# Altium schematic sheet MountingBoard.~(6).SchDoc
size Legal; Organization: Altium Limited; Address1: 3 Minna Close; Address2: Belrose; Address3: NSW 2085; Address4: Australia
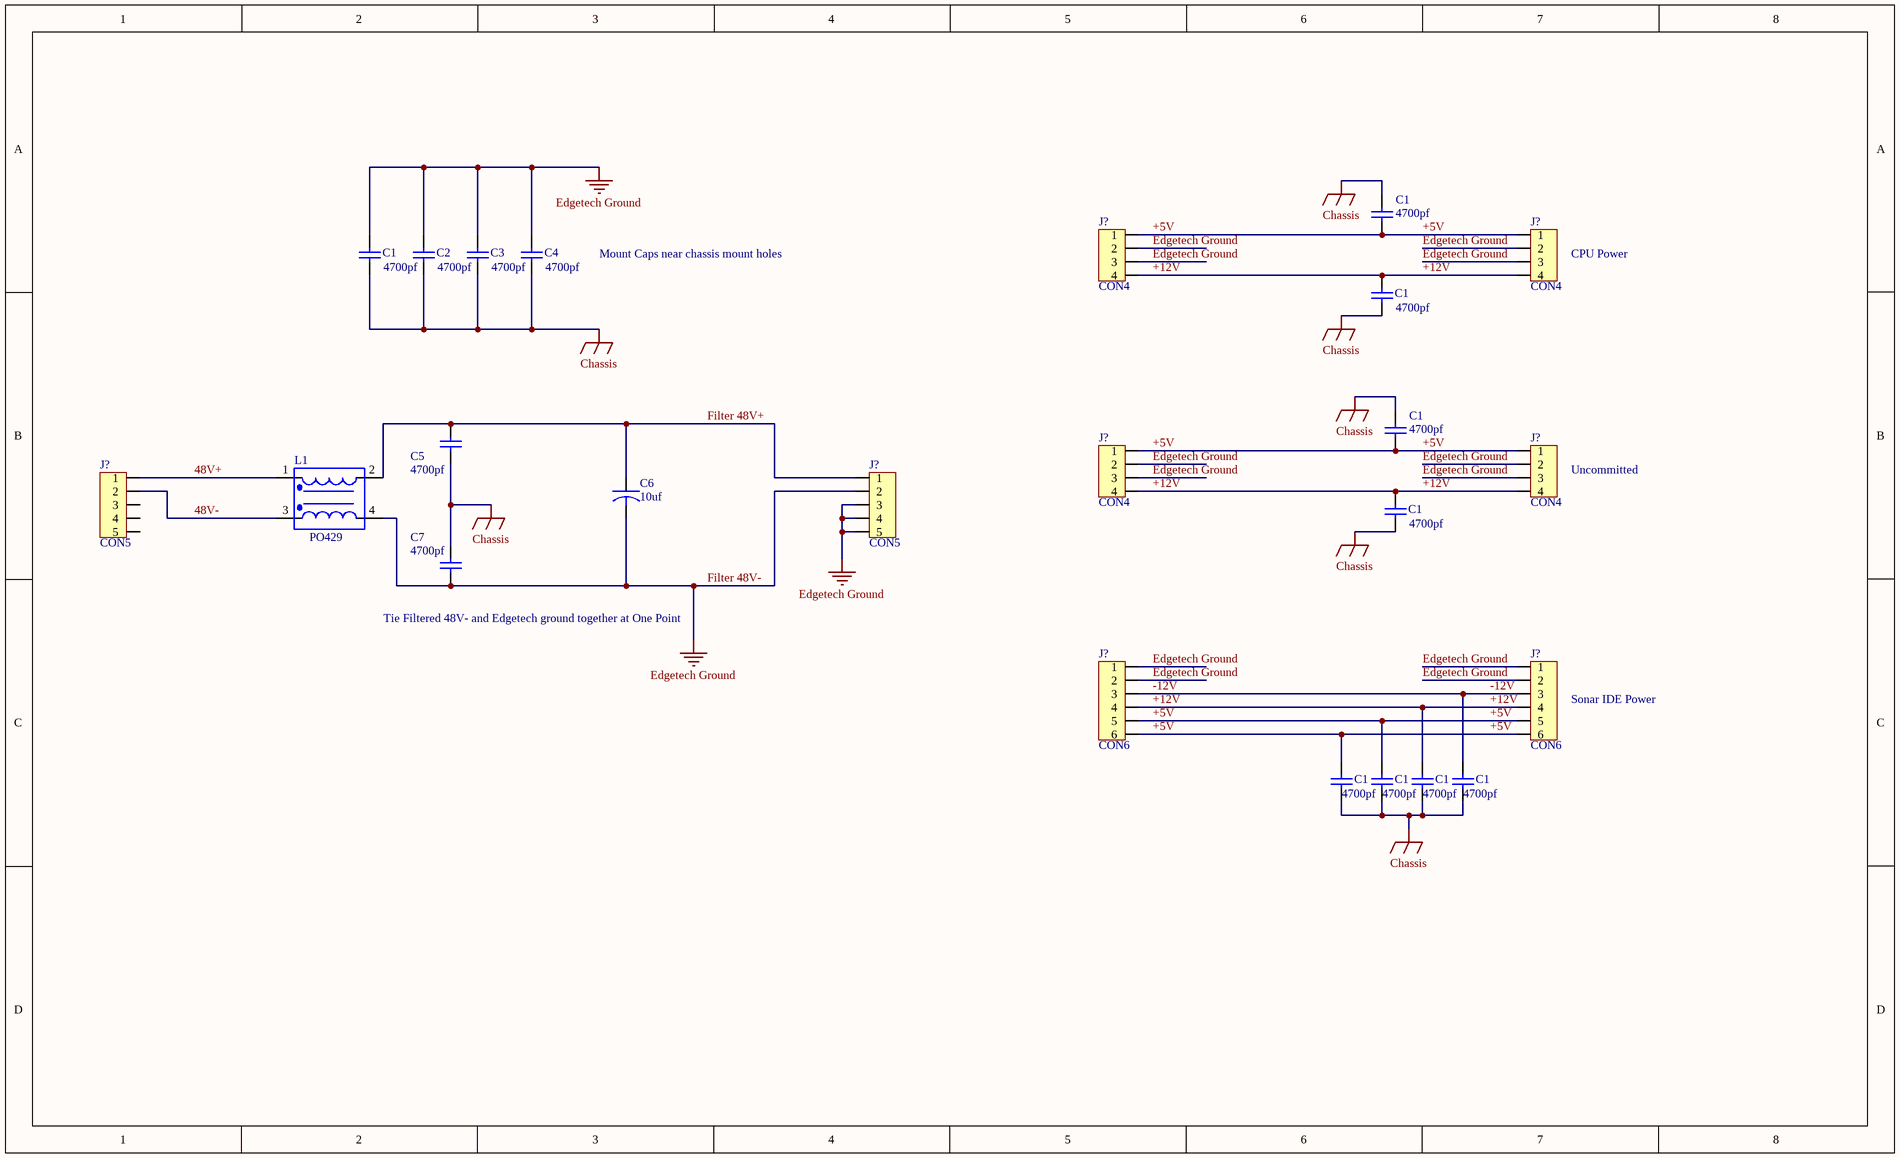
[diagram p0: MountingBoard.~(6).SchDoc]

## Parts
(Parts that share a designator on the sheet are numbered #1, #2 ... from top to bottom, then left to right.)
C1#1  value 4700pf  [CAPC3216L]  (hidden comment: Cap Semi)
C1#2  value 4700pf  [CAPC3216L]  (hidden comment: Cap Semi)
C1#3  value 4700pf  [CAPC3216L]  (hidden comment: Cap Semi)
C1#4  value 4700pf  [CAPC3216L]  (hidden comment: Cap Semi)
C1#5  value 4700pf  [CAPC3216L]  (hidden comment: Cap Semi)
C1#6  value 4700pf  [CAPC3216L]  (hidden comment: Cap Semi)
C1#7  value 4700pf  [CAPC3216L]  (hidden comment: Cap Semi)
C1#8  value 4700pf  [CAPC3216L]  (hidden comment: Cap Semi)
C1#9  value 4700pf  [CAPC3216L]  (hidden comment: Cap Semi)
C2  value 4700pf  [CAPC3216L]  (hidden comment: Cap Semi)
C3  value 4700pf  [CAPC3216L]  (hidden comment: Cap Semi)
C4  value 4700pf  [CAPC3216L]  (hidden comment: Cap Semi)
C5  value 4700pf  [CAPC3216L]  (hidden comment: Cap Semi)
C6  10uf  [CAPSTICK-CS4-7-SMD]
C7  value 4700pf  [CAPC3216L]  (hidden comment: Cap Semi)
J?#1  CON4  [SIP4]
J?#2  CON4  [SIP4]
J?#3  CON4  [SIP4]
J?#4  CON4  [SIP4]
J?#5  CON5  [SIP5]
J?#6  CON5  [SIP5]
J?#7  CON6  [SIP6]
J?#8  CON6  [SIP6]
L1  ManufPartNo: PO429  [Pulse_BigFoot]

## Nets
Chassis: C1#1.2 C1#2.1 C1#3.1 C1#4.2 C1#5.1 C1#6.1 C1#7.1 C1#8.1 C1#9.1 C2.1 C3.1 C4.1 C5.1 C7.2
Edgetech Ground: C1#2.2 C2.2 C3.2 C4.2 C6.2 C7.1 J?#1.2 J?#1.3 J?#2.2 J?#2.3 J?#3.2 J?#3.3 J?#4.2 J?#4.3 J?#6.2 J?#6.3 J?#6.4 J?#6.5 J?#7.1 J?#7.2 J?#8.1 J?#8.2 L1.4  [also labelled Filter 48V-]
48V+: J?#5.1 L1.1
48V-: J?#5.2 L1.3
+5V: C1#1.1 C1#4.1 C1#6.2 C1#7.2 J?#1.1 J?#2.1 J?#3.1 J?#4.1 J?#7.5 J?#7.6 J?#8.5 J?#8.6
+12V: C1#3.2 C1#5.2 C1#8.2 J?#1.4 J?#2.4 J?#3.4 J?#4.4 J?#7.4 J?#8.4
-12V: C1#9.2 J?#7.3 J?#8.3
Filter 48V+: C5.2 C6.1 J?#6.1 L1.2

Not connected (* = marked no-connect by the designer): J?#5 3 4 5

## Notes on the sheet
- Mount Caps near chassis mount holes
- (near J?#2) CPU Power
- (near J?#4) Uncommitted
- (near C7) Tie Filtered 48V- and Edgetech ground together at One Point
- (near J?#8) Sonar IDE Power

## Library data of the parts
C1#1-C1#9 C2-C5 C7 = Cap Semi: Capacitor (Semiconductor SIM Model)
C6 = CAPACITOR: ManufPartNo: 106K100CS4G; Manufacturer: ITW Paktron; Vendor: Future Electronics; Value: 10
J?#1-J?#4 = CON4: Connector
J?#5 J?#6 = CON5: Connector
J?#7 J?#8 = CON6: Connector
L1 = COMMON MODE CHOKE: Manufacturer: Pulse Engineering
